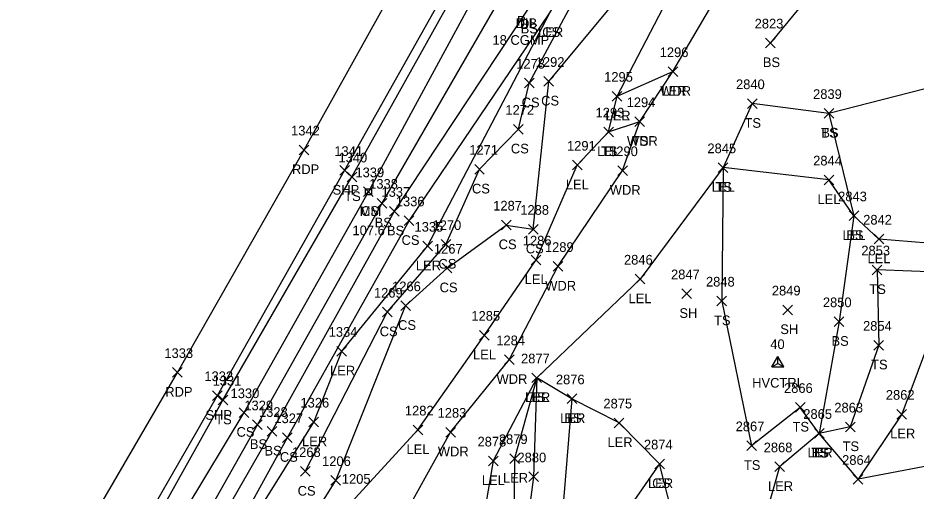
# Model space of a CAD drawing. Extents: x 1483143 to 1488182, y 802902 to 807581.
# Drawn here: x 1487266.4 to 1487452.4, y 805291.1 to 805389.1 of the extents above; entities that cross this region are included whole.
import ezdxf

# ---------------------------------------------------------------- set-up
doc = ezdxf.new("R2010")
doc.units = 0
for name, color, linetype in [('C_A', 7, 'Continuous'), ('C_I', 7, 'Continuous'), ('CPSM', 7, 'Continuous'), ('D_A', 7, 'Continuous'), ('D_C', 7, 'Continuous'), ('L_A', 7, 'Continuous'), ('L_I', 7, 'Continuous'), ('L_TIC', 7, 'Continuous'), ('LARO', 7, 'Continuous'), ('LAWA', 7, 'Continuous'), ('LELB', 7, 'Continuous'), ('P_A', 7, 'Continuous'), ('P_I', 7, 'Continuous'), ('P_TIC', 7, 'Continuous'), ('PET', 7, 'Continuous'), ('PSP', 7, 'Continuous'), ('S_A', 7, 'Continuous'), ('S_C', 7, 'Continuous'), ('S_I', 7, 'Continuous'), ('SRM', 7, 'Continuous')]:
    doc.layers.add(name, color=color, linetype=linetype)

msp = doc.modelspace()

# ---------------------------------------------------------------- linework, layer by layer
at = {"layer": 'CPSM'}
for p, q in [((1487422.55, 805316.8), (1487423.8, 805318.97)), ((1487422.55, 805316.8), (1487423.81, 805317.52)), ((1487425.05, 805316.8), (1487423.8, 805318.97)), ((1487423.81, 805317.52), (1487423.8, 805318.97)), ((1487423.81, 805317.52), (1487423.81, 805317.52)), ((1487423.81, 805317.52), (1487425.05, 805316.8)), ((1487422.55, 805316.8), (1487425.05, 805316.8))]:
    msp.add_line(p, q, dxfattribs=at)
at = {"layer": 'L_TIC'}
for points in [[(1487421.27, 805382.88), (1487423.27, 805384.88)], [(1487423.27, 805382.88), (1487421.27, 805384.88)], [(1487401.1, 805376.95), (1487403.1, 805378.95)], [(1487403.1, 805376.95), (1487401.1, 805378.95)], [(1487401.1, 805376.95), (1487403.1, 805378.95)], [(1487403.1, 805376.95), (1487401.1, 805378.95)], [(1487375.36, 805374.93), (1487377.36, 805376.93)], [(1487377.36, 805374.93), (1487375.36, 805376.93)], [(1487371.32, 805374.57), (1487373.32, 805376.57)], [(1487373.32, 805374.57), (1487371.32, 805376.57)], [(1487389.53, 805371.85), (1487391.53, 805373.85)], [(1487391.53, 805371.85), (1487389.53, 805373.85)], [(1487389.53, 805371.85), (1487391.53, 805373.85)], [(1487391.53, 805371.85), (1487389.53, 805373.85)], [(1487417.5, 805370.32), (1487419.5, 805372.32)], [(1487419.5, 805370.32), (1487417.5, 805372.32)], [(1487433.38, 805368.29), (1487435.38, 805370.29)], [(1487435.38, 805368.29), (1487433.38, 805370.29)], [(1487433.38, 805368.29), (1487435.38, 805370.29)], [(1487435.38, 805368.29), (1487433.38, 805370.29)], [(1487394.2, 805366.59), (1487396.2, 805368.59)], [(1487396.2, 805366.59), (1487394.2, 805368.59)], [(1487394.2, 805366.59), (1487396.2, 805368.59)], [(1487396.2, 805366.59), (1487394.2, 805368.59)], [(1487369.08, 805365.01), (1487371.08, 805367.01)], [(1487371.08, 805365.01), (1487369.08, 805367.01)], [(1487387.76, 805364.45), (1487389.76, 805366.45)], [(1487389.76, 805364.45), (1487387.76, 805366.45)], [(1487387.76, 805364.45), (1487389.76, 805366.45)], [(1487389.76, 805364.45), (1487387.76, 805366.45)], [(1487361.03, 805356.72), (1487363.03, 805358.72)], [(1487363.03, 805356.72), (1487361.03, 805358.72)], [(1487381.28, 805357.58), (1487383.28, 805359.58)], [(1487383.28, 805357.58), (1487381.28, 805359.58)], [(1487390.65, 805356.45), (1487392.65, 805358.45)], [(1487392.65, 805356.45), (1487390.65, 805358.45)], [(1487411.49, 805357.06), (1487413.49, 805359.06)], [(1487413.49, 805357.06), (1487411.49, 805359.06)], [(1487411.49, 805357.06), (1487413.49, 805359.06)], [(1487413.49, 805357.06), (1487411.49, 805359.06)], [(1487334.6, 805355.15), (1487336.6, 805357.15)], [(1487336.6, 805355.15), (1487334.6, 805357.15)], [(1487433.38, 805354.52), (1487435.38, 805356.52)], [(1487435.38, 805354.52), (1487433.38, 805356.52)], [(1487338.04, 805352.08), (1487340.04, 805354.08)], [(1487340.04, 805352.08), (1487338.04, 805354.08)], [(1487340.87, 805349.7), (1487342.87, 805351.7)], [(1487342.87, 805349.7), (1487340.87, 805351.7)], [(1487343.42, 805348.03), (1487345.42, 805350.03)], [(1487345.42, 805348.03), (1487343.42, 805350.03)], [(1487438.56, 805347.1), (1487440.56, 805349.1)], [(1487440.56, 805347.1), (1487438.56, 805349.1)], [(1487438.56, 805347.1), (1487440.56, 805349.1)], [(1487440.56, 805347.1), (1487438.56, 805349.1)], [(1487346.45, 805346.07), (1487348.45, 805348.07)], [(1487348.45, 805346.07), (1487346.45, 805348.07)], [(1487366.56, 805345.19), (1487368.56, 805347.19)], [(1487368.56, 805345.19), (1487366.56, 805347.19)], [(1487372.17, 805344.31), (1487374.17, 805346.31)], [(1487374.17, 805344.31), (1487372.17, 805346.31)], [(1487443.75, 805342.28), (1487445.75, 805344.28)], [(1487445.75, 805342.28), (1487443.75, 805344.28)], [(1487350.27, 805340.81), (1487352.27, 805342.81)], [(1487352.27, 805340.81), (1487350.27, 805342.81)], [(1487354.08, 805341.16), (1487356.08, 805343.16)], [(1487356.08, 805341.16), (1487354.08, 805343.16)], [(1487372.75, 805337.95), (1487374.75, 805339.95)], [(1487374.75, 805337.95), (1487372.75, 805339.95)], [(1487354.33, 805336.27), (1487356.33, 805338.27)], [(1487356.33, 805336.27), (1487354.33, 805338.27)], [(1487377.28, 805336.62), (1487379.28, 805338.62)], [(1487379.28, 805336.62), (1487377.28, 805338.62)], [(1487443.36, 805335.9), (1487445.36, 805337.9)], [(1487445.36, 805335.9), (1487443.36, 805337.9)], [(1487394.27, 805334), (1487396.27, 805336)], [(1487396.27, 805334), (1487394.27, 805336)], [(1487403.95, 805330.96), (1487405.95, 805332.96)], [(1487405.95, 805330.96), (1487403.95, 805332.96)], [(1487345.73, 805328.48), (1487347.73, 805330.48)], [(1487347.73, 805328.48), (1487345.73, 805330.48)], [(1487411.19, 805329.45), (1487413.19, 805331.45)], [(1487413.19, 805329.45), (1487411.19, 805331.45)], [(1487341.92, 805327.16), (1487343.92, 805329.16)], [(1487343.92, 805327.16), (1487341.92, 805329.16)], [(1487424.83, 805327.61), (1487426.83, 805329.61)], [(1487426.83, 805327.61), (1487424.83, 805329.61)], [(1487435.49, 805325.18), (1487437.49, 805327.18)], [(1487437.49, 805325.18), (1487435.49, 805327.18)], [(1487362.04, 805322.38), (1487364.04, 805324.38)], [(1487364.04, 805322.38), (1487362.04, 805324.38)], [(1487443.72, 805320.3), (1487445.72, 805322.3)], [(1487445.72, 805320.3), (1487443.72, 805322.3)], [(1487332.49, 805319.05), (1487334.49, 805321.05)], [(1487334.49, 805319.05), (1487332.49, 805321.05)], [(1487367.2, 805317.3), (1487369.2, 805319.3)], [(1487369.2, 805317.3), (1487367.2, 805319.3)], [(1487372.89, 805313.55), (1487374.89, 805315.55)], [(1487374.89, 805313.55), (1487372.89, 805315.55)], [(1487372.89, 805313.55), (1487374.89, 805315.55)], [(1487374.89, 805313.55), (1487372.89, 805315.55)], [(1487372.89, 805313.55), (1487374.89, 805315.55)], [(1487374.89, 805313.55), (1487372.89, 805315.55)], [(1487307.89, 805308.94), (1487309.89, 805310.94)], [(1487309.89, 805308.94), (1487307.89, 805310.94)], [(1487380.16, 805309.21), (1487382.16, 805311.21)], [(1487382.16, 805309.21), (1487380.16, 805311.21)], [(1487380.16, 805309.21), (1487382.16, 805311.21)], [(1487382.16, 805309.21), (1487380.16, 805311.21)], [(1487312.26, 805306.35), (1487314.26, 805308.35)], [(1487314.26, 805306.35), (1487312.26, 805308.35)], [(1487427.45, 805307.43), (1487429.45, 805309.43)], [(1487429.45, 805307.43), (1487427.45, 805309.43)], [(1487326.69, 805304.4), (1487328.69, 805306.4)], [(1487328.69, 805304.4), (1487326.69, 805306.4)], [(1487448.49, 805306.02), (1487450.49, 805308.02)], [(1487450.49, 805306.02), (1487448.49, 805308.02)], [(1487315.03, 805303.83), (1487317.03, 805305.83)], [(1487317.03, 805303.83), (1487315.03, 805305.83)], [(1487318.05, 805302.47), (1487320.05, 805304.47)], [(1487320.05, 805302.47), (1487318.05, 805304.47)], [(1487348.28, 805302.76), (1487350.28, 805304.76)], [(1487350.28, 805302.76), (1487348.28, 805304.76)], [(1487389.95, 805304.22), (1487391.95, 805306.22)], [(1487391.95, 805304.22), (1487389.95, 805306.22)], [(1487437.81, 805303.38), (1487439.81, 805305.38)], [(1487439.81, 805303.38), (1487437.81, 805305.38)], [(1487321.25, 805301.17), (1487323.25, 805303.17)], [(1487323.25, 805301.17), (1487321.25, 805303.17)], [(1487355.05, 805302.3), (1487357.05, 805304.3)], [(1487357.05, 805302.3), (1487355.05, 805304.3)], [(1487431.38, 805302.06), (1487433.38, 805304.06)], [(1487433.38, 805302.06), (1487431.38, 805304.06)], [(1487431.38, 805302.06), (1487433.38, 805304.06)], [(1487433.38, 805302.06), (1487431.38, 805304.06)], [(1487431.38, 805302.06), (1487433.38, 805304.06)], [(1487433.38, 805302.06), (1487431.38, 805304.06)], [(1487417.38, 805299.5), (1487419.38, 805301.5)], [(1487419.38, 805299.5), (1487417.38, 805301.5)], [(1487417.38, 805299.5), (1487419.38, 805301.5)], [(1487419.38, 805299.5), (1487417.38, 805301.5)], [(1487368.31, 805296.84), (1487370.31, 805298.84)], [(1487370.31, 805296.84), (1487368.31, 805298.84)], [(1487363.88, 805296.34), (1487365.88, 805298.34)], [(1487365.88, 805296.34), (1487363.88, 805298.34)], [(1487398.34, 805295.74), (1487400.34, 805297.74)], [(1487400.34, 805295.74), (1487398.34, 805297.74)], [(1487398.34, 805295.74), (1487400.34, 805297.74)], [(1487400.34, 805295.74), (1487398.34, 805297.74)], [(1487423.19, 805295.14), (1487425.19, 805297.14)], [(1487425.19, 805295.14), (1487423.19, 805297.14)], [(1487324.93, 805294.16), (1487326.93, 805296.16)], [(1487326.93, 805294.16), (1487324.93, 805296.16)], [(1487331.26, 805292.3), (1487333.26, 805294.3)], [(1487333.26, 805292.3), (1487331.26, 805294.3)], [(1487372.24, 805293.06), (1487374.24, 805295.06)], [(1487374.24, 805293.06), (1487372.24, 805295.06)], [(1487439.44, 805292.54), (1487441.44, 805294.54)], [(1487441.44, 805292.54), (1487439.44, 805294.54)], [(1487439.44, 805292.54), (1487441.44, 805294.54)], [(1487441.44, 805292.54), (1487439.44, 805294.54)]]:
    msp.add_lwpolyline(points, dxfattribs=at)
at = {"layer": 'LARO'}
for points in [[(1487124.31, 804973.13), (1487145.49, 805006.81), (1487169.77, 805044.38), (1487180.59, 805057.87), (1487189.8, 805070.17), (1487199.3, 805080.96), (1487217.89, 805101.74), (1487229.45, 805124.32), (1487246.83, 805150.76), (1487254.41, 805169.19), (1487269.28, 805204.96), (1487282.34, 805212.7), (1487284.63, 805226.5), (1487290.62, 805235.83), (1487297.31, 805243.76), (1487306.73, 805267.09), (1487309.81, 805276.71), (1487327.69, 805305.4), (1487333.49, 805320.05), (1487351.27, 805341.81), (1487376.58, 805390.13), (1487400.9, 805431.24), (1487423.77, 805476.17), (1487448.72, 805522.61)], [(1487275.82, 805186.86), (1487281.82, 805201.01), (1487291.77, 805208.89), (1487296.21, 805220.88), (1487297.4, 805236.19), (1487306.61, 805244.48), (1487316.03, 805247.44), (1487325.53, 805270.19), (1487336.29, 805289.62), (1487349.28, 805303.76), (1487363.04, 805323.38), (1487373.75, 805338.95), (1487382.28, 805358.58), (1487388.76, 805365.45), (1487390.53, 805372.85), (1487405.19, 805401.03), (1487414.25, 805416.49), (1487427.8, 805437.51), (1487440.02, 805462.35), (1487458.8, 805482.34), (1487468.72, 805503.53)], [(1487491.14, 805377.64), (1487483.45, 805387.21), (1487470.89, 805380.76), (1487466.26, 805367.22), (1487470.78, 805358.6), (1487458.23, 805342.16), (1487444.75, 805343.28), (1487439.56, 805348.1), (1487434.38, 805355.52), (1487412.49, 805358.06), (1487395.27, 805335), (1487373.89, 805314.55), (1487364.88, 805297.34), (1487361.7, 805278.72), (1487355.69, 805264.09), (1487356.67, 805249.84), (1487363.34, 805255.29)], [(1487390.53, 805372.85), (1487402.1, 805377.95)], [(1487456.25, 805325.1), (1487449.49, 805307.02), (1487440.44, 805293.54), (1487432.38, 805303.06), (1487424.19, 805296.14), (1487419.05, 805278.13), (1487404.37, 805277), (1487399.34, 805296.74), (1487390.95, 805305.22), (1487381.16, 805310.21), (1487373.89, 805314.55), (1487369.31, 805297.84), (1487368.9, 805261.33), (1487363.34, 805255.29)]]:
    msp.add_lwpolyline(points, dxfattribs=at)
at = {"layer": 'LAWA'}
msp.add_lwpolyline([(1487288.55, 805192.53), (1487294.52, 805206.51), (1487300.85, 805219.32), (1487309.39, 805232.65), (1487323.83, 805245.51), (1487330.77, 805260.07), (1487338.78, 805272.82), (1487344.77, 805283.02), (1487356.05, 805303.3), (1487368.2, 805318.3), (1487378.28, 805337.62), (1487391.65, 805357.45), (1487395.2, 805367.59), (1487402.1, 805377.95), (1487420, 805408.55), (1487434.6, 805433.13), (1487446.38, 805459.81), (1487458.8, 805482.34), (1487472.47, 805498.82)], dxfattribs=at)
at = {"layer": 'LELB'}
for points in [[(1487199.3, 805080.96), (1487209.02, 805107.06), (1487224.53, 805127.21), (1487240.95, 805152.24), (1487249.95, 805171.94), (1487269.65, 805210.5), (1487285.86, 805237.33), (1487303.36, 805267.84), (1487322.25, 805302.17), (1487347.45, 805347.07), (1487376.58, 805390.13), (1487398.58, 805433.78), (1487419.88, 805479.75), (1487445.41, 805524.09), (1487470.45, 805569.86), (1487486.06, 805603.16), (1487492.1, 805615.56), (1487500.68, 805632.42), (1487507.33, 805640.17), (1487520.3, 805671.34), (1487528.77, 805686.31), (1487539.17, 805698.49)], [(1487494, 805544.66), (1487489.98, 805516.76), (1487483.1, 805499.99), (1487469.62, 805485.44), (1487459.73, 805470.37), (1487454.06, 805447.12), (1487466.58, 805438.47), (1487460.53, 805427.6), (1487458.79, 805393.78), (1487437.28, 805402.12), (1487422.27, 805383.88)], [(1487108.71, 804980.78), (1487132.66, 805016.32), (1487156.92, 805053.98), (1487173.31, 805079.98), (1487194.46, 805114.79), (1487207.05, 805135.95), (1487220.86, 805159.73), (1487233.38, 805181.3), (1487254.33, 805216.27), (1487271.44, 805245.69), (1487289.79, 805275.85), (1487308.89, 805309.94), (1487335.6, 805356.15), (1487359.27, 805398.59), (1487383.94, 805443.57), (1487406.66, 805485.41), (1487431.45, 805531.24)], [(1487141.45, 805012.57), (1487160.97, 805051.58), (1487177.59, 805077.87), (1487198.8, 805111.86), (1487211.59, 805133.5), (1487225.91, 805156.73), (1487238.62, 805176.26), (1487258.28, 805214.16), (1487275.11, 805243.36), (1487293.13, 805273.9), (1487313.26, 805307.35), (1487339.04, 805353.08), (1487362.83, 805397.01), (1487388.55, 805442.86), (1487410.04, 805483.24), (1487436.07, 805529.53)], [(1487115.55, 804977.3), (1487141.45, 805012.57), (1487163.51, 805049.72), (1487181.31, 805075.62), (1487202.21, 805110.17), (1487217.83, 805130.45), (1487232, 805156.36), (1487242.54, 805175.79), (1487260.94, 805211.88), (1487278.65, 805241.13), (1487296.94, 805270.92), (1487316.03, 805304.83), (1487341.87, 805350.7), (1487367.6, 805395.34), (1487392.63, 805437.94), (1487413.83, 805481.53), (1487440.22, 805526.89)], [(1487119.27, 804975.75), (1487145.32, 805010.11), (1487166.09, 805047.54), (1487184.56, 805073.64), (1487204.9, 805108.12), (1487221.47, 805128.3), (1487235.08, 805155.22), (1487247.48, 805170.55), (1487262.97, 805210.14), (1487282.96, 805240.11), (1487299.52, 805269.42), (1487319.05, 805303.47), (1487344.42, 805349.03), (1487372.12, 805390.86), (1487397.58, 805436.46), (1487417, 805480.8), (1487442.28, 805525.8)], [(1487325.93, 805295.16), (1487342.92, 805328.16), (1487355.08, 805342.16), (1487362.03, 805357.72), (1487370.08, 805366.01), (1487372.32, 805375.57), (1487382.82, 805395.1), (1487393.76, 805413), (1487404.56, 805433.17), (1487408.6, 805436.76), (1487418.34, 805454.56), (1487419.92, 805460.14), (1487427.79, 805468.84), (1487429.21, 805476.67), (1487428.48, 805479.23), (1487445.24, 805504.83)], [(1487306.61, 805244.48), (1487309.54, 805255.21), (1487320.74, 805274.89), (1487332.26, 805293.3), (1487346.73, 805329.48), (1487355.33, 805337.27), (1487367.56, 805346.19), (1487373.17, 805345.31), (1487376.36, 805375.93), (1487391.59, 805394.26), (1487397.32, 805413.81), (1487403.03, 805424.17), (1487412.59, 805429.38), (1487414.66, 805438.85), (1487433.83, 805470.6), (1487438.06, 805486.56), (1487449.51, 805502.69)], [(1487498.95, 805499.29), (1487498.64, 805474.67), (1487497.23, 805443.74), (1487505.04, 805441.72), (1487510.17, 805435.4), (1487504.77, 805417.91), (1487493.48, 805388.2), (1487491.14, 805377.64), (1487487.41, 805369.48), (1487480.75, 805361.74), (1487474.3, 805355.43), (1487470.84, 805329.04), (1487477.5, 805318.33), (1487486.09, 805303.62), (1487460.83, 805297.42), (1487440.44, 805293.54)], [(1487469.62, 805485.44), (1487470.04, 805467.97), (1487479.88, 805464.48), (1487486.36, 805449.24), (1487481.8, 805426.69), (1487480.51, 805392.58), (1487470.89, 805380.76), (1487459.41, 805375.67), (1487434.38, 805369.29), (1487418.5, 805371.32), (1487412.49, 805358.06), (1487412.19, 805330.45), (1487418.38, 805300.5)], [(1487483.45, 805387.21), (1487474.71, 805367.25), (1487470.78, 805358.6), (1487459.23, 805335.43), (1487458.6, 805336.35), (1487444.36, 805336.9), (1487444.72, 805321.3), (1487438.81, 805304.38), (1487432.38, 805303.06), (1487428.45, 805308.43), (1487418.38, 805300.5)], [(1487434.38, 805369.29), (1487439.56, 805348.1), (1487436.49, 805326.18), (1487432.38, 805303.06)], [(1487388.76, 805365.45), (1487395.2, 805367.59)], [(1487373.89, 805314.55), (1487373.24, 805294.06), (1487368.9, 805261.33), (1487361.57, 805264.43), (1487361.7, 805278.72)], [(1487381.16, 805310.21), (1487379.1, 805284.98), (1487376.67, 805247.37), (1487363.34, 805255.29)], [(1487399.34, 805296.74), (1487386.35, 805278.05), (1487385.19, 805259.93), (1487397.46, 805244.02)]]:
    msp.add_lwpolyline(points, dxfattribs=at)
at = {"layer": 'P_TIC'}
for points in [[(1487324.71, 805360.73), (1487326.71, 805362.73)], [(1487326.71, 805360.73), (1487324.71, 805362.73)], [(1487333.08, 805356.49), (1487335.08, 805358.49)], [(1487335.08, 805356.49), (1487333.08, 805358.49)], [(1487298.46, 805314.66), (1487300.46, 805316.66)], [(1487300.46, 805314.66), (1487298.46, 805316.66)], [(1487306.74, 805309.87), (1487308.74, 805311.87)], [(1487308.74, 805309.87), (1487306.74, 805311.87)]]:
    msp.add_lwpolyline(points, dxfattribs=at)
at = {"layer": 'PET'}
msp.add_lwpolyline([(1487100.01, 804984.32), (1487124.37, 805022.55), (1487148.19, 805060.93), (1487163.62, 805085.69), (1487185.29, 805121.77), (1487197.78, 805142.12), (1487211.62, 805165.78), (1487224.01, 805186.83), (1487244.77, 805222.1), (1487262.9, 805253.28), (1487279.63, 805281.48), (1487299.46, 805315.66), (1487325.71, 805361.73), (1487348.03, 805401.83), (1487373.61, 805448.47), (1487396.33, 805490.41), (1487421.9, 805537.94)], dxfattribs=at)
at = {"layer": 'PSP'}
msp.add_lwpolyline([(1487105.23, 804982.13), (1487129.96, 805018.35), (1487154.68, 805055.53), (1487171.02, 805081.93), (1487192.51, 805116.63), (1487204.72, 805136.95), (1487219.03, 805160.88), (1487231.84, 805182.51), (1487252.47, 805217.19), (1487269.89, 805246.6), (1487288.3, 805277.02), (1487307.74, 805310.87), (1487334.08, 805357.49), (1487356.35, 805397.12), (1487382.38, 805444.5), (1487405.03, 805486.21), (1487429.8, 805532.42)], dxfattribs=at)
at = {"layer": 'SRM'}
msp.add_lwpolyline([(1487338.42, 805353.71), (1487339.67, 805353.71), (1487339.67, 805352.46), (1487338.42, 805352.46)], close=True, dxfattribs=at)
msp.add_circle((1487339.04, 805353.08), 0.0833, dxfattribs=at)

# ---------------------------------------------------------------- texts
at = {"layer": 'C_A'}
msp.add_text('HVCTRL', height=2, dxfattribs=at).set_placement((1487418.5, 805312.52))
at = {"layer": 'C_I'}
msp.add_text('40', height=2, dxfattribs=at).set_placement((1487422.25, 805320.52))
at = {"layer": 'D_A'}
for s, p in [('DIB', (1487369.51, 805386.97)), ('P', (1487369.81, 805387.49)), ('DI', (1487370.42, 805386.91))]:
    msp.add_text(s, height=2, dxfattribs=at).set_placement(p)
at = {"layer": 'D_C'}
msp.add_text('18 CGMP', height=2, dxfattribs=at).set_placement((1487364.72, 805383.49))
at = {"layer": 'L_A'}
for s, p in [('BS', (1487370.56, 805385.86)), ('LER', (1487374.16, 805385.13)), ('CS', (1487375.02, 805385.13)), ('BS', (1487420.71, 805378.88)), ('WDR', (1487399.46, 805372.95)), ('LER', (1487399.69, 805372.95)), ('CS', (1487370.76, 805370.57)), ('CS', (1487374.8, 805370.93)), ('LER', (1487388.11, 805367.85)), ('LEL', (1487388.17, 805367.85)), ('TS', (1487416.91, 805366.32)), ('TS', (1487432.79, 805364.29)), ('BS', (1487432.82, 805364.29)), ('WDR', (1487392.56, 805362.59)), ('TS', (1487393.61, 805362.59)), ('CS', (1487368.52, 805361.01)), ('LEL', (1487386.4, 805360.45)), ('TS', (1487387.17, 805360.45)), ('CS', (1487360.47, 805352.72)), ('LEL', (1487379.91, 805353.58)), ('LEL', (1487410.13, 805353.06)), ('TS', (1487410.9, 805353.06)), ('TS', (1487334.01, 805351.15)), ('WDR', (1487389.01, 805352.45)), ('LEL', (1487432.02, 805350.52)), ('CS', (1487337.48, 805348.08)), ('BS', (1487340.31, 805345.7)), ('BS', (1487342.86, 805344.03)), ('CS', (1487345.89, 805342.07)), ('LEL', (1487437.2, 805343.1)), ('BS', (1487438, 805343.1)), ('CS', (1487366, 805341.19)), ('CS', (1487371.62, 805340.31)), ('LEL', (1487442.39, 805338.28)), ('LER', (1487348.85, 805336.81)), ('CS', (1487353.52, 805337.16)), ('CS', (1487353.77, 805332.27)), ('LEL', (1487371.39, 805333.95)), ('WDR', (1487375.65, 805332.62)), ('TS', (1487442.77, 805331.9)), ('LEL', (1487392.9, 805330)), ('SH', (1487403.44, 805326.96)), ('TS', (1487410.6, 805325.45)), ('CS', (1487341.36, 805323.16)), ('CS', (1487345.17, 805324.48)), ('SH', (1487424.32, 805323.61)), ('BS', (1487434.93, 805321.18)), ('LEL', (1487360.68, 805318.38)), ('TS', (1487443.13, 805316.3)), ('LER', (1487331.08, 805315.05)), ('WDR', (1487365.56, 805313.3)), ('LER', (1487371.47, 805309.55)), ('LEL', (1487371.52, 805309.55)), ('TS', (1487372.3, 805309.55)), ('TS', (1487307.29, 805304.94)), ('LER', (1487378.74, 805305.21)), ('BS', (1487379.6, 805305.21)), ('TS', (1487426.86, 805303.43)), ('CS', (1487311.71, 805302.35)), ('LER', (1487447.07, 805302.02)), ('BS', (1487314.47, 805299.83)), ('LER', (1487325.28, 805300.4)), ('LEL', (1487346.91, 805298.76)), ('LER', (1487388.53, 805300.22)), ('TS', (1487437.22, 805299.38)), ('BS', (1487317.5, 805298.47)), ('CS', (1487320.69, 805297.17)), ('WDR', (1487353.41, 805298.3)), ('LER', (1487429.97, 805298.06)), ('TS', (1487430.79, 805298.06)), ('BS', (1487430.82, 805298.06)), ('TS', (1487416.79, 805295.5)), ('TS', (1487416.79, 805295.5)), ('LEL', (1487362.52, 805292.34)), ('LER', (1487366.89, 805292.84)), ('LER', (1487396.93, 805291.74)), ('CS', (1487397.79, 805291.74)), ('CS', (1487324.37, 805290.16)), ('LER', (1487421.77, 805291.14))]:
    msp.add_text(s, height=2, dxfattribs=at).set_placement(p)
at = {"layer": 'L_I'}
for s, p in [('2823', (1487419.01, 805386.88)), ('1296', (1487399.35, 805380.95)), ('1296', (1487399.35, 805380.95)), ('1292', (1487373.67, 805378.93)), ('1273', (1487369.63, 805378.57)), ('1295', (1487387.84, 805375.85)), ('1295', (1487387.84, 805375.85)), ('2840', (1487415.15, 805374.32)), ('2839', (1487431.11, 805372.29)), ('2839', (1487431.11, 805372.29)), ('1294', (1487392.5, 805370.59)), ('1294', (1487392.5, 805370.59)), ('1272', (1487367.39, 805369.01)), ('1293', (1487386.07, 805368.45)), ('1293', (1487386.07, 805368.45)), ('1271', (1487359.91, 805360.72)), ('1291', (1487380.15, 805361.58)), ('1290', (1487388.87, 805360.45)), ('2845', (1487409.23, 805361.06)), ('2845', (1487409.23, 805361.06)), ('1340', (1487332.82, 805359.15)), ('2844', (1487431.13, 805358.52)), ('1339', (1487336.34, 805356.08)), ('1338', (1487339.18, 805353.7)), ('1337', (1487341.73, 805352.03)), ('2843', (1487436.3, 805351.1)), ('2843', (1487436.3, 805351.1)), ('1336', (1487344.7, 805350.07)), ('1287', (1487364.87, 805349.19)), ('1288', (1487370.48, 805348.31)), ('1270', (1487352.3, 805345.16)), ('2842', (1487441.49, 805346.28)), ('1335', (1487348.57, 805344.81)), ('1286', (1487371, 805341.95)), ('1267', (1487352.59, 805340.27)), ('1289', (1487375.58, 805340.62)), ('2853', (1487441.1, 805339.9)), ('2846', (1487391.95, 805338)), ('2847', (1487401.69, 805334.96)), ('1266', (1487343.93, 805332.48)), ('2848', (1487408.93, 805333.45)), ('1269', (1487340.17, 805331.16)), ('2849', (1487422.57, 805331.61)), ('2850', (1487433.14, 805329.18)), ('1285', (1487360.35, 805326.38)), ('1334', (1487330.8, 805323.05)), ('2854', (1487441.46, 805324.3)), ('1284', (1487365.51, 805321.3)), ('2877', (1487370.63, 805317.55)), ('2877', (1487370.63, 805317.55)), ('2877', (1487370.63, 805317.55)), ('1331', (1487306.76, 805312.94)), ('2876', (1487377.85, 805313.21)), ('2876', (1487377.85, 805313.21)), ('1330', (1487310.48, 805310.35)), ('2866', (1487425.09, 805311.43)), ('2862', (1487446.18, 805310.02)), ('1326', (1487324.95, 805308.4)), ('2875', (1487387.69, 805308.22)), ('1329', (1487313.33, 805307.83)), ('1328', (1487316.36, 805306.47)), ('1282', (1487346.58, 805306.76)), ('1283', (1487353.35, 805306.3)), ('2863', (1487435.51, 805307.38)), ('1327', (1487319.55, 805305.17)), ('2865', (1487429.08, 805306.06)), ('2865', (1487429.08, 805306.06)), ('2865', (1487429.08, 805306.06)), ('2867', (1487415.08, 805303.5)), ('2867', (1487415.08, 805303.5)), ('2879', (1487366.04, 805300.84)), ('2878', (1487361.62, 805300.34)), ('2874', (1487396.08, 805299.74)), ('2874', (1487396.08, 805299.74)), ('2868', (1487420.88, 805299.14)), ('1268', (1487323.19, 805298.16)), ('2880', (1487369.89, 805297.06)), ('1206', (1487329.43, 805296.3)), ('2864', (1487437.13, 805296.54)), ('2864', (1487437.13, 805296.54)), ('1205', (1487333.52, 805292.62))]:
    msp.add_text(s, height=2, dxfattribs=at).set_placement(p)
at = {"layer": 'P_A'}
for s, p in [('RDP', (1487323.19, 805356.73)), ('SHP', (1487331.62, 805352.49)), ('RDP', (1487296.95, 805310.66)), ('SHP', (1487305.28, 805305.87))]:
    msp.add_text(s, height=2, dxfattribs=at).set_placement(p)
at = {"layer": 'P_I'}
for s, p in [('1342', (1487323.01, 805364.73)), ('1341', (1487331.96, 805360.49)), ('1333', (1487296.77, 805318.66)), ('1332', (1487305.05, 805313.87))]:
    msp.add_text(s, height=2, dxfattribs=at).set_placement(p)
at = {"layer": 'S_A'}
msp.add_text('MM', height=2, dxfattribs=at).set_placement((1487337.23, 805348.08))
at = {"layer": 'S_C'}
msp.add_text('107.6', height=2, dxfattribs=at).set_placement((1487335.73, 805344.08))
at = {"layer": 'S_I'}
msp.add_text('1339', height=2, dxfattribs=at).set_placement((1487336.34, 805356.08))

doc.saveas('drawing.dxf')
